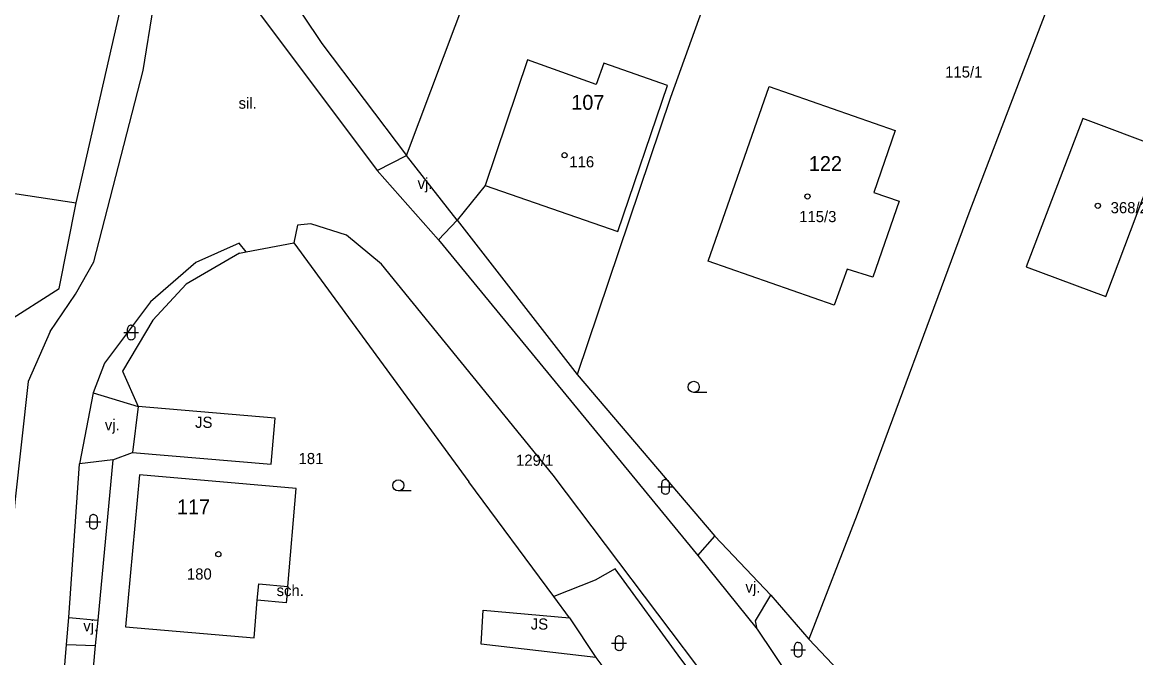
# Model space of a CAD drawing. Extents: x -836739 to -835945, y -1070775 to -1070126.
# Drawn here: x -836533 to -836458, y -1070491.8 to -1070449 of the extents above; entities that cross this region are included whole.
import ezdxf

# ---------------------------------------------------------------- set-up
doc = ezdxf.new("R2010")
doc.units = 0
for name, color, linetype in [('BodPole_mer', 7, 'Continuous'), ('Budovy_hranice', 7, 'Continuous'), ('Budovy_kody', 7, 'Continuous'), ('Doprava_hranice', 7, 'Continuous'), ('Doprava_kody', 7, 'Continuous'), ('OstPloch_kody', 7, 'Continuous'), ('RuianAdr_popis', 7, 'Continuous'), ('RuianPar_popis', 7, 'Continuous'), ('Stavby_hr_schod', 7, 'Continuous'), ('Stavby_hr_stav', 7, 'Continuous'), ('Stavby_kody', 7, 'Continuous'), ('Stavby_linie', 7, 'Continuous')]:
    doc.layers.add(name, color=color, linetype=linetype)

msp = doc.modelspace()

# ---------------------------------------------------------------- linework, layer by layer
at = {"layer": 'BodPole_mer'}
for p, q in [((-836512.81, -1070450.42), (-836512.81, -1070450.42)), ((-836498.95, -1070451.52), (-836498.95, -1070451.52)), ((-836493.81, -1070451.74), (-836493.81, -1070451.74)), ((-836524.83, -1070452.23), (-836524.83, -1070452.23)), ((-836494.32, -1070453.18), (-836494.32, -1070453.18)), ((-836489.52, -1070453.24), (-836489.52, -1070453.24)), ((-836482.66, -1070453.32), (-836482.66, -1070453.32)), ((-836489.31, -1070454.06), (-836489.31, -1070454.06)), ((-836461.55, -1070455.46), (-836461.55, -1070455.46)), ((-836474.18, -1070456.28), (-836474.18, -1070456.28)), ((-836507.11, -1070457.97), (-836507.11, -1070457.97)), ((-836509.08, -1070458.97), (-836509.08, -1070458.97)), ((-836501.8, -1070459.98), (-836501.8, -1070459.98)), ((-836475.62, -1070460.46), (-836475.62, -1070460.46)), ((-836473.91, -1070461.04), (-836473.91, -1070461.04)), ((-836529.34, -1070461.16), (-836529.34, -1070461.16)), ((-836513.54, -1070462.56), (-836513.54, -1070462.56)), ((-836503.69, -1070462.32), (-836503.69, -1070462.32)), ((-836469.22, -1070461.85), (-836469.22, -1070461.85)), ((-836514.44, -1070462.65), (-836514.44, -1070462.65)), ((-836511.15, -1070463.33), (-836511.15, -1070463.33)), ((-836492.87, -1070463.09), (-836492.87, -1070463.09)), ((-836518.36, -1070463.86), (-836518.36, -1070463.86)), ((-836514.68, -1070463.85), (-836514.68, -1070463.85)), ((-836504.94, -1070463.64), (-836504.94, -1070463.64)), ((-836518.35, -1070464.55), (-836518.35, -1070464.55)), ((-836517.9, -1070464.46), (-836517.9, -1070464.46)), ((-836528.17, -1070465.13), (-836528.17, -1070465.13)), ((-836521.29, -1070465.17), (-836521.29, -1070465.17)), ((-836508.79, -1070465.29), (-836508.79, -1070465.29)), ((-836486.79, -1070465.09), (-836486.79, -1070465.09)), ((-836465.35, -1070465.47), (-836465.35, -1070465.47)), ((-836477.41, -1070465.61), (-836477.41, -1070465.61)), ((-836475.68, -1070466.15), (-836475.68, -1070466.15)), ((-836530.49, -1070466.92), (-836530.49, -1070466.92)), ((-836521.93, -1070466.63), (-836521.93, -1070466.63)), ((-836529.4, -1070467.3), (-836529.4, -1070467.3)), ((-836524.35, -1070467.82), (-836524.35, -1070467.82)), ((-836460, -1070467.47), (-836460, -1070467.47)), ((-836478.29, -1070468.05), (-836478.29, -1070468.05)), ((-836524.18, -1070469.06), (-836524.18, -1070469.06)), ((-836531.1, -1070469.82), (-836531.1, -1070469.82)), ((-836527.43, -1070471.96), (-836527.43, -1070471.96)), ((-836526.22, -1070472.48), (-836526.22, -1070472.48)), ((-836495.6, -1070472.71), (-836495.6, -1070472.71)), ((-836532.59, -1070473.19), (-836532.59, -1070473.19)), ((-836528.2, -1070473.94), (-836528.2, -1070473.94)), ((-836525.18, -1070474.87), (-836525.18, -1070474.87)), ((-836515.95, -1070475.65), (-836515.95, -1070475.65)), ((-836525.55, -1070477.96), (-836525.55, -1070477.96)), ((-836529.13, -1070478.74), (-836529.13, -1070478.74)), ((-836526.89, -1070478.47), (-836526.89, -1070478.47)), ((-836516.22, -1070478.75), (-836516.22, -1070478.75)), ((-836525.09, -1070479.47), (-836525.09, -1070479.47)), ((-836497.22, -1070479.49), (-836497.22, -1070479.49)), ((-836514.52, -1070480.4), (-836514.52, -1070480.4)), ((-836502.89, -1070479.95), (-836502.89, -1070479.95)), ((-836476.75, -1070482.14), (-836476.75, -1070482.14)), ((-836486.33, -1070483.6), (-836486.33, -1070483.6)), ((-836487.47, -1070484.91), (-836487.47, -1070484.91)), ((-836493.05, -1070485.81), (-836493.05, -1070485.81)), ((-836494.38, -1070486.57), (-836494.38, -1070486.57)), ((-836517.05, -1070486.82), (-836517.05, -1070486.82)), ((-836515.1, -1070486.99), (-836515.1, -1070486.99)), ((-836517.15, -1070487.92), (-836517.15, -1070487.92)), ((-836497.18, -1070487.66), (-836497.18, -1070487.66)), ((-836482.56, -1070487.59), (-836482.56, -1070487.59)), ((-836515.2, -1070488.1), (-836515.2, -1070488.1)), ((-836501.93, -1070488.59), (-836501.93, -1070488.59)), ((-836529.84, -1070489.08), (-836529.84, -1070489.08)), ((-836527.9, -1070489.26), (-836527.9, -1070489.26)), ((-836496.11, -1070489.11), (-836496.11, -1070489.11)), ((-836483.59, -1070489.3), (-836483.59, -1070489.3)), ((-836526.03, -1070489.71), (-836526.03, -1070489.71)), ((-836483.47, -1070489.88), (-836483.47, -1070489.88)), ((-836529.99, -1070490.91), (-836529.99, -1070490.91)), ((-836528.06, -1070490.96), (-836528.06, -1070490.96)), ((-836517.37, -1070490.45), (-836517.37, -1070490.45)), ((-836502.06, -1070490.89), (-836502.06, -1070490.89)), ((-836479.99, -1070490.54), (-836479.99, -1070490.54)), ((-836494.34, -1070491.77), (-836494.34, -1070491.77))]:
    msp.add_line(p, q, dxfattribs=at)
at = {"layer": 'Budovy_hranice'}
for points in [[(-836498.95, -1070451.52), (-836501.8, -1070459.98), (-836492.87, -1070463.09), (-836489.52, -1070453.24), (-836493.81, -1070451.74), (-836494.32, -1070453.18), (-836498.95, -1070451.52)], [(-836478.29, -1070468.05), (-836486.79, -1070465.09), (-836482.66, -1070453.32), (-836474.18, -1070456.28), (-836475.62, -1070460.46), (-836473.91, -1070461.04), (-836475.68, -1070466.15), (-836477.41, -1070465.61), (-836478.29, -1070468.05)], [(-836456.23, -1070457.47), (-836461.55, -1070455.46), (-836465.35, -1070465.47), (-836460, -1070467.47), (-836456.23, -1070457.47)], [(-836517.15, -1070487.92), (-836517.05, -1070486.82), (-836515.1, -1070486.99), (-836514.52, -1070480.4), (-836525.09, -1070479.47), (-836526.03, -1070489.71), (-836517.37, -1070490.45), (-836517.15, -1070487.92)]]:
    msp.add_lwpolyline(points, dxfattribs=at)
at = {"layer": 'Budovy_kody'}
for centre in [(-836496.45, -1070457.94), (-836480.09, -1070460.72), (-836460.53, -1070461.35), (-836519.77, -1070484.82)]:
    msp.add_circle(centre, 0.175, dxfattribs=at)
at = {"layer": 'Doprava_hranice'}
for p, q in [((-836509.08, -1070458.97), (-836507.11, -1070457.97)), ((-836509.08, -1070458.97), (-836504.94, -1070463.64)), ((-836503.69, -1070462.32), (-836504.94, -1070463.64)), ((-836528.2, -1070473.94), (-836525.18, -1070474.87)), ((-836526.89, -1070478.47), (-836529.13, -1070478.74)), ((-836487.47, -1070484.91), (-836486.33, -1070483.6)), ((-836529.84, -1070489.08), (-836527.9, -1070489.26)), ((-836529.99, -1070490.91), (-836528.06, -1070490.96))]:
    msp.add_line(p, q, dxfattribs=at)
for points in [[(-836531.1, -1070469.82), (-836529.4, -1070467.3), (-836528.17, -1070465.13), (-836524.83, -1070452.23), (-836524.15, -1070447.92), (-836523.94, -1070446.04), (-836523.89, -1070443.38), (-836524.1, -1070441.71), (-836524.87, -1070438.13), (-836528.78, -1070429.39), (-836535.78, -1070414.25), (-836542.47, -1070401.26), (-836543.02, -1070395.42), (-836542.75, -1070393.88), (-836540.03, -1070384.3)], [(-836520.08, -1070438.65), (-836520.32, -1070439.15), (-836520.23, -1070444.07), (-836509.08, -1070458.97)], [(-836457.12, -1070544.57), (-836455.91, -1070543.66), (-836455.92, -1070541.81), (-836461.09, -1070532.63), (-836472.09, -1070514.53), (-836483.11, -1070498.19), (-836497.22, -1070479.49), (-836508.79, -1070465.29), (-836511.15, -1070463.33), (-836513.54, -1070462.56), (-836514.44, -1070462.65), (-836514.68, -1070463.85)], [(-836517.9, -1070464.46), (-836518.36, -1070463.86), (-836521.29, -1070465.17), (-836524.35, -1070467.82), (-836527.43, -1070471.96), (-836528.2, -1070473.94), (-836529.13, -1070478.74)], [(-836504.94, -1070463.64), (-836487.47, -1070484.91), (-836483.47, -1070489.88), (-836478.99, -1070496.57), (-836476.3, -1070501.37), (-836473.79, -1070505.61), (-836465.77, -1070518.73), (-836447.09, -1070550.1), (-836449.85, -1070551.69), (-836449.97, -1070560.65)], [(-836531.1, -1070469.82), (-836532.59, -1070473.19), (-836533.47, -1070481.32), (-836533.93, -1070486.76), (-836533.99, -1070488.23), (-836534.36, -1070493.24), (-836535.73, -1070507.97), (-836536.22, -1070513.12), (-836536.82, -1070520.24), (-836537.38, -1070525.89), (-836537.98, -1070532.4), (-836538.73, -1070540.19), (-836539.5, -1070548.26)], [(-836535.55, -1070551.78), (-836534.99, -1070545.87), (-836532.78, -1070522.39), (-836532.06, -1070514.59), (-836531.14, -1070504.66), (-836530.74, -1070499.84), (-836530.27, -1070494.21), (-836529.99, -1070490.91), (-836529.84, -1070489.08), (-836529.13, -1070478.74)], [(-836483.47, -1070489.88), (-836483.59, -1070489.3), (-836482.56, -1070487.59)]]:
    msp.add_lwpolyline(points, dxfattribs=at)
at = {"layer": 'OstPloch_kody'}
for p, q in [((-836526.14, -1070469.89), (-836525.14, -1070469.89)), ((-836525.89, -1070470.14), (-836525.89, -1070469.64)), ((-836525.39, -1070469.64), (-836525.39, -1070470.14)), ((-836486.875, -1070473.92), (-836487.75, -1070473.92)), ((-836506.775, -1070480.56), (-836507.65, -1070480.56)), ((-836490.16, -1070480.29), (-836489.16, -1070480.29)), ((-836489.91, -1070480.54), (-836489.91, -1070480.04)), ((-836489.41, -1070480.04), (-836489.41, -1070480.54)), ((-836528.69, -1070482.64), (-836527.69, -1070482.64)), ((-836528.44, -1070482.89), (-836528.44, -1070482.39)), ((-836527.94, -1070482.39), (-836527.94, -1070482.89)), ((-836493.28, -1070490.82), (-836492.28, -1070490.82)), ((-836493.03, -1070491.07), (-836493.03, -1070490.57)), ((-836492.53, -1070490.57), (-836492.53, -1070491.07)), ((-836480.97, -1070491.51), (-836480.97, -1070491.01)), ((-836480.47, -1070491.01), (-836480.47, -1070491.51)), ((-836481.22, -1070491.26), (-836480.22, -1070491.26))]:
    msp.add_line(p, q, dxfattribs=at)
for points in [[(-836525.64, -1070469.39), (-836525.685, -1070469.394), (-836525.732, -1070469.408), (-836525.777, -1070469.431), (-836525.817, -1070469.463), (-836525.849, -1070469.503), (-836525.872, -1070469.548), (-836525.886, -1070469.595), (-836525.89, -1070469.64)], [(-836525.64, -1070469.39), (-836525.595, -1070469.394), (-836525.548, -1070469.408), (-836525.503, -1070469.431), (-836525.463, -1070469.463), (-836525.431, -1070469.503), (-836525.408, -1070469.548), (-836525.394, -1070469.595), (-836525.39, -1070469.64)], [(-836525.64, -1070470.39), (-836525.685, -1070470.386), (-836525.732, -1070470.372), (-836525.777, -1070470.349), (-836525.817, -1070470.317), (-836525.849, -1070470.277), (-836525.872, -1070470.232), (-836525.886, -1070470.185), (-836525.89, -1070470.14)], [(-836525.39, -1070470.14), (-836525.394, -1070470.185), (-836525.408, -1070470.232), (-836525.431, -1070470.277), (-836525.463, -1070470.317), (-836525.503, -1070470.349), (-836525.548, -1070470.372), (-836525.595, -1070470.386), (-836525.64, -1070470.39)], [(-836489.66, -1070479.79), (-836489.705, -1070479.794), (-836489.752, -1070479.808), (-836489.797, -1070479.831), (-836489.837, -1070479.863), (-836489.869, -1070479.903), (-836489.892, -1070479.948), (-836489.906, -1070479.995), (-836489.91, -1070480.04)], [(-836489.66, -1070479.79), (-836489.615, -1070479.794), (-836489.568, -1070479.808), (-836489.523, -1070479.831), (-836489.483, -1070479.863), (-836489.451, -1070479.903), (-836489.428, -1070479.948), (-836489.414, -1070479.995), (-836489.41, -1070480.04)], [(-836489.66, -1070480.79), (-836489.705, -1070480.786), (-836489.752, -1070480.772), (-836489.797, -1070480.749), (-836489.837, -1070480.717), (-836489.869, -1070480.677), (-836489.892, -1070480.632), (-836489.906, -1070480.585), (-836489.91, -1070480.54)], [(-836489.41, -1070480.54), (-836489.414, -1070480.585), (-836489.428, -1070480.632), (-836489.451, -1070480.677), (-836489.483, -1070480.717), (-836489.523, -1070480.749), (-836489.568, -1070480.772), (-836489.615, -1070480.786), (-836489.66, -1070480.79)], [(-836528.19, -1070482.14), (-836528.235, -1070482.144), (-836528.282, -1070482.158), (-836528.327, -1070482.181), (-836528.367, -1070482.213), (-836528.399, -1070482.253), (-836528.422, -1070482.298), (-836528.436, -1070482.345), (-836528.44, -1070482.39)], [(-836528.19, -1070482.14), (-836528.145, -1070482.144), (-836528.098, -1070482.158), (-836528.053, -1070482.181), (-836528.013, -1070482.213), (-836527.981, -1070482.253), (-836527.958, -1070482.298), (-836527.944, -1070482.345), (-836527.94, -1070482.39)], [(-836528.19, -1070483.14), (-836528.235, -1070483.136), (-836528.282, -1070483.122), (-836528.327, -1070483.099), (-836528.367, -1070483.067), (-836528.399, -1070483.027), (-836528.422, -1070482.982), (-836528.436, -1070482.935), (-836528.44, -1070482.89)], [(-836527.94, -1070482.89), (-836527.944, -1070482.935), (-836527.958, -1070482.982), (-836527.981, -1070483.027), (-836528.013, -1070483.067), (-836528.053, -1070483.099), (-836528.098, -1070483.122), (-836528.145, -1070483.136), (-836528.19, -1070483.14)], [(-836492.78, -1070490.32), (-836492.825, -1070490.324), (-836492.872, -1070490.338), (-836492.917, -1070490.361), (-836492.957, -1070490.393), (-836492.989, -1070490.433), (-836493.012, -1070490.478), (-836493.026, -1070490.525), (-836493.03, -1070490.57)], [(-836492.78, -1070490.32), (-836492.735, -1070490.324), (-836492.688, -1070490.338), (-836492.643, -1070490.361), (-836492.603, -1070490.393), (-836492.571, -1070490.433), (-836492.548, -1070490.478), (-836492.534, -1070490.525), (-836492.53, -1070490.57)], [(-836492.78, -1070491.32), (-836492.825, -1070491.316), (-836492.872, -1070491.302), (-836492.917, -1070491.279), (-836492.957, -1070491.247), (-836492.989, -1070491.207), (-836493.012, -1070491.162), (-836493.026, -1070491.115), (-836493.03, -1070491.07)], [(-836492.53, -1070491.07), (-836492.534, -1070491.115), (-836492.548, -1070491.162), (-836492.571, -1070491.207), (-836492.603, -1070491.247), (-836492.643, -1070491.279), (-836492.688, -1070491.302), (-836492.735, -1070491.316), (-836492.78, -1070491.32)], [(-836480.72, -1070490.76), (-836480.765, -1070490.764), (-836480.812, -1070490.778), (-836480.857, -1070490.801), (-836480.897, -1070490.833), (-836480.929, -1070490.873), (-836480.952, -1070490.918), (-836480.966, -1070490.965), (-836480.97, -1070491.01)], [(-836480.72, -1070490.76), (-836480.675, -1070490.764), (-836480.628, -1070490.778), (-836480.583, -1070490.801), (-836480.543, -1070490.833), (-836480.511, -1070490.873), (-836480.488, -1070490.918), (-836480.474, -1070490.965), (-836480.47, -1070491.01)], [(-836480.72, -1070491.76), (-836480.765, -1070491.756), (-836480.812, -1070491.742), (-836480.857, -1070491.719), (-836480.897, -1070491.687), (-836480.929, -1070491.647), (-836480.952, -1070491.602), (-836480.966, -1070491.555), (-836480.97, -1070491.51)], [(-836480.47, -1070491.51), (-836480.474, -1070491.555), (-836480.488, -1070491.602), (-836480.511, -1070491.647), (-836480.543, -1070491.687), (-836480.583, -1070491.719), (-836480.628, -1070491.742), (-836480.675, -1070491.756), (-836480.72, -1070491.76)]]:
    msp.add_lwpolyline(points, dxfattribs=at)
for centre in [(-836487.75, -1070473.545), (-836507.65, -1070480.185)]:
    msp.add_ellipse(centre, major_axis=(0.375, 0), ratio=0.999999, dxfattribs=at)
at = {"layer": 'RuianAdr_popis'}
for p, q in [((-836496, -1070454.88), (-836496, -1070454.88)), ((-836480, -1070459), (-836480, -1070459)), ((-836522.56, -1070482.13), (-836522.56, -1070482.13))]:
    msp.add_line(p, q, dxfattribs=at)
at = {"layer": 'RuianPar_popis'}
for p, q in [((-836470.82, -1070452.71), (-836470.82, -1070452.71)), ((-836496.13, -1070458.76), (-836496.13, -1070458.76)), ((-836480.65, -1070462.45), (-836480.65, -1070462.45)), ((-836459.67, -1070461.85), (-836459.67, -1070461.85)), ((-836514.37, -1070478.75), (-836514.37, -1070478.75)), ((-836499.72, -1070478.86), (-836499.72, -1070478.86)), ((-836521.89, -1070486.53), (-836521.89, -1070486.53))]:
    msp.add_line(p, q, dxfattribs=at)
at = {"layer": 'Stavby_hr_schod'}
msp.add_lwpolyline([(-836515.1, -1070486.99), (-836515.2, -1070488.1), (-836517.15, -1070487.92)], dxfattribs=at)
at = {"layer": 'Stavby_hr_stav'}
for points in [[(-836525.55, -1070477.96), (-836516.22, -1070478.75), (-836515.95, -1070475.65), (-836525.18, -1070474.87), (-836525.55, -1070477.96)], [(-836496.11, -1070489.11), (-836494.34, -1070491.77), (-836502.06, -1070490.89), (-836501.93, -1070488.59), (-836496.11, -1070489.11)]]:
    msp.add_lwpolyline(points, dxfattribs=at)
at = {"layer": 'Stavby_linie'}
for p, q in [((-836503.69, -1070462.32), (-836507.11, -1070457.97)), ((-836501.8, -1070459.98), (-836503.69, -1070462.32)), ((-836503.69, -1070462.32), (-836495.6, -1070472.71)), ((-836514.68, -1070463.85), (-836502.89, -1070479.95)), ((-836526.22, -1070472.48), (-836525.18, -1070474.87)), ((-836495.6, -1070472.71), (-836486.33, -1070483.6)), ((-836526.89, -1070478.47), (-836525.55, -1070477.96)), ((-836486.33, -1070483.6), (-836482.56, -1070487.59)), ((-836482.56, -1070487.59), (-836479.99, -1070490.54)), ((-836479.99, -1070490.54), (-836476.23, -1070494.52)), ((-836494.34, -1070491.77), (-836492.51, -1070494.2))]:
    msp.add_line(p, q, dxfattribs=at)
for points in [[(-836449.39, -1070412.25), (-836456.32, -1070429.46), (-836463.2, -1070446.07), (-836469.22, -1070461.85), (-836476.75, -1070482.14), (-836479.99, -1070490.54)], [(-836507.11, -1070457.97), (-836501.33, -1070442.61), (-836500.5, -1070440.27)], [(-836519.03, -1070441.12), (-836512.81, -1070450.42), (-836507.11, -1070457.97)], [(-836485.34, -1070443), (-836489.31, -1070454.06), (-836495.6, -1070472.71)], [(-836535.29, -1070481.63), (-836535.24, -1070481.2), (-836534.16, -1070469.25), (-836530.49, -1070466.92), (-836529.34, -1070461.16), (-836525.7, -1070445.11)], [(-836558.53, -1070456.83), (-836546.69, -1070458.52), (-836529.34, -1070461.16)], [(-836518.35, -1070464.55), (-836517.9, -1070464.46), (-836514.68, -1070463.85)], [(-836518.35, -1070464.55), (-836521.93, -1070466.63), (-836524.18, -1070469.06), (-836526.22, -1070472.48)], [(-836526.89, -1070478.47), (-836527.9, -1070489.26), (-836528.06, -1070490.96), (-836528.34, -1070493.98)], [(-836496.11, -1070489.11), (-836497.18, -1070487.66), (-836502.89, -1070479.95)], [(-836487.65, -1070500.92), (-836484.55, -1070500.48), (-836484.73, -1070499.09), (-836485.28, -1070497.73), (-836485, -1070496.62), (-836488.61, -1070491.86), (-836493.05, -1070485.81), (-836494.38, -1070486.57), (-836497.18, -1070487.66)]]:
    msp.add_lwpolyline(points, dxfattribs=at)

# ---------------------------------------------------------------- texts
at = {"layer": 'Doprava_kody'}
for s, p in [('sil.', (-836518.41, -1070454.81)), ('vj.', (-836506.35, -1070460.22)), ('vj.', (-836527.42, -1070476.48)), ('vj.', (-836484.27, -1070487.41)), ('vj.', (-836528.87, -1070490.02))]:
    msp.add_text(s, height=0.75, dxfattribs=at).set_placement(p)
at = {"layer": 'RuianAdr_popis'}
for s, p in [('107', (-836496, -1070454.88)), ('122', (-836480, -1070459)), ('117', (-836522.56, -1070482.13))]:
    msp.add_text(s, height=1, dxfattribs=at).set_placement(p)
at = {"layer": 'RuianPar_popis'}
for s, p in [('115/1', (-836470.82, -1070452.71)), ('116', (-836496.13, -1070458.76)), ('368/21', (-836459.67, -1070461.85)), ('115/3', (-836480.65, -1070462.45)), ('181', (-836514.37, -1070478.75)), ('129/1', (-836499.72, -1070478.86)), ('180', (-836521.89, -1070486.53))]:
    msp.add_text(s, height=0.75, dxfattribs=at).set_placement(p)
at = {"layer": 'Stavby_kody'}
for s, p in [('JS', (-836521.34, -1070476.31)), ('sch.', (-836515.85, -1070487.64)), ('JS', (-836498.73, -1070489.9))]:
    msp.add_text(s, height=0.75, dxfattribs=at).set_placement(p)

doc.saveas('drawing.dxf')
